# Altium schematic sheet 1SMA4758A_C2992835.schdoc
size 127 x 101 mm
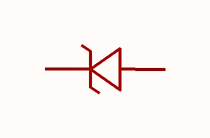
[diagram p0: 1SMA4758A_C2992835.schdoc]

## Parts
D?  1sma4758a_c2992835  [SMA_L4.3-W2.5-LS5.0-RD]  (value not drawn)

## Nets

Not connected (* = marked no-connect by the designer): D? 1(C) 2(A)

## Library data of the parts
D? = 1sma4758a_c2992835: 二极管配置:1个独立式;稳压值(标称值):56V;稳压值(范围):53.6V~58.8V;耗散功率(Pd):1W;; Manufacturer: MDD(辰达半导体); AddInBom: yes; ModelId: 5b53cc1b87a148cc9fa13125be89f948; ModelTransform: 194.8815,98.425,0,0,0,0,0,0,0; Diode Configuration: 1个独立式; Zener Voltage(Nom): 56V; Reverse Leakage Current (Ir): 1uA@42V; Pd - Power Dissipation: 1W; Impedance(Zzt): 110Ω; Operating Junction Temperature Range: -55℃~+150℃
